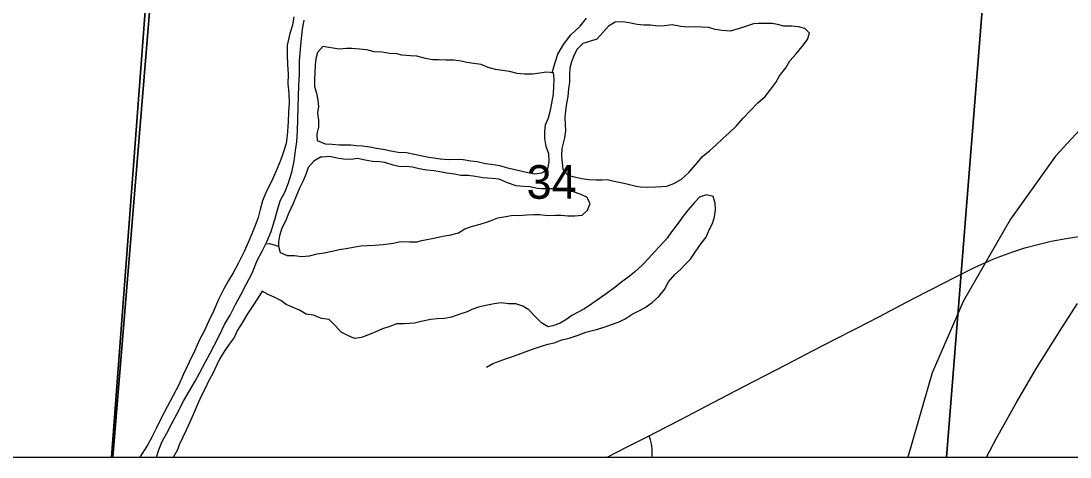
# Model space of a CAD drawing. Extents: x 0 to 1067, y 0 to 440.
# Drawn here: x 799.345 to 800.649, y 350.802 to 351.344 of the extents above; entities that cross this region are included whole.
import ezdxf

# ---------------------------------------------------------------- set-up
doc = ezdxf.new("R2010")
doc.units = 0
for name, color, linetype in [('GM_X_Major_River', 7, 'Continuous'), ('GM_X_Minor_Lake', 7, 'Continuous'), ('GM_X_Minor_River', 7, 'Continuous'), ('GM_X_Rail_Line', 7, 'Continuous'), ('GM_X_Section_Text', 7, 'Continuous'), ('GM_X_State_Route', 7, 'Continuous'), ('GM_X_Township_Road', 7, 'Continuous'), ('GM_X_US_Shield', 7, 'Continuous')]:
    doc.layers.add(name, color=color, linetype=linetype)

msp = doc.modelspace()

# ---------------------------------------------------------------- linework, layer by layer
at = {"layer": 'GM_X_Major_River'}
for points in [[(799.6839, 351.3498), (799.6825, 351.3392), (799.6789, 351.329), (799.6756, 351.3142), (799.6758, 351.3024), (799.6763, 351.2903), (799.6769, 351.2785), (799.6766, 351.2663), (799.6776, 351.2545), (799.6781, 351.2423), (799.6775, 351.2317), (799.6769, 351.2184), (799.6758, 351.202), (799.6745, 351.1921), (799.6713, 351.1819), (799.6673, 351.171), (799.6613, 351.1562), (799.6561, 351.1449), (799.6498, 351.1321), (799.645, 351.1208), (799.6422, 351.1098), (799.6397, 351.0999), (799.6361, 351.0901), (799.6317, 351.0799), (799.6273, 351.069), (799.6222, 351.0576), (799.6147, 351.0429), (799.6084, 351.0312), (799.6028, 351.0215), (799.5969, 351.0113), (799.5902, 350.9981)], [(799.5389, 350.8563), (799.5472, 350.8722), (799.5543, 350.8846), (799.5613, 350.8963), (799.5668, 350.9064), (799.5743, 350.9204), (799.5795, 350.9306), (799.585, 350.9407), (799.5917, 350.9536), (799.598, 350.9671), (799.6047, 350.9784), (799.6114, 350.992), (799.6185, 351.0048), (799.6248, 351.0165), (799.6323, 351.0308), (799.6383, 351.0467), (799.6446, 351.058), (799.6506, 351.0697), (799.6558, 351.0825), (799.6606, 351.0977), (799.6635, 351.1079), (799.6671, 351.1208), (799.673, 351.1317), (799.6774, 351.143), (799.6815, 351.1563), (799.6844, 351.1699), (799.6862, 351.1832), (799.6879, 351.1942), (799.6885, 351.2079), (799.6892, 351.2223), (799.6897, 351.2512), (799.6903, 351.2634), (799.691, 351.2786), (799.6909, 351.2942), (799.6918, 351.3044), (799.6932, 351.3185), (799.695, 351.3341), (799.6967, 351.3454)], [(799.5902, 350.9981), (799.5843, 350.9837), (799.5783, 350.9717), (799.5724, 350.9585), (799.5668, 350.9479), (799.5609, 350.9347), (799.5538, 350.92), (799.5466, 350.9045), (799.541, 350.8917), (799.5269, 350.8653), (799.519, 350.8506), (799.513, 350.8374), (799.5075, 350.8268), (799.502, 350.817), (799.4953, 350.8065), (799.4926, 350.8021)], [(799.5132, 350.8021), (799.5163, 350.8111), (799.5203, 350.8213), (799.5259, 350.8318), (799.5329, 350.8446), (799.5389, 350.8563)]]:
    msp.add_lwpolyline(points, dxfattribs=at)
at = {"layer": 'GM_X_Minor_Lake'}
for points in [[(800.2609, 351.2426), (800.2702, 351.2506), (800.2771, 351.2596), (800.2833, 351.2679), (800.288, 351.2762), (800.2957, 351.2863), (800.3008, 351.295), (800.3089, 351.3036), (800.3162, 351.3127), (800.3228, 351.3213), (800.3252, 351.3292), (800.3195, 351.335), (800.3116, 351.337), (800.3029, 351.3379), (800.2934, 351.338), (800.2854, 351.34), (800.279, 351.3412), (800.2615, 351.3415), (800.2558, 351.3408), (800.2459, 351.3375), (800.2368, 351.3346), (800.2265, 351.3317), (800.2166, 351.3326), (800.2079, 351.3338), (800.2, 351.3362), (800.1916, 351.3367), (800.1829, 351.3372), (800.1746, 351.3369), (800.1651, 351.3378), (800.1545, 351.3395), (800.145, 351.3385), (800.1366, 351.3382), (800.1275, 351.3391), (800.1192, 351.3392), (800.1108, 351.34), (800.101, 351.3421), (800.0926, 351.3433), (800.0835, 351.3431), (800.0755, 351.3382), (800.0685, 351.33), (800.0608, 351.3217), (800.0517, 351.3188), (800.0433, 351.3163), (800.036, 351.3091), (800.0321, 351.3012), (800.0293, 351.2936), (800.0273, 351.2857), (800.0268, 351.2774), (800.0267, 351.2682), (800.0258, 351.2599), (800.0249, 351.2504), (800.0233, 351.2417), (800.022, 351.2326), (800.0211, 351.2243), (800.0214, 351.2155), (800.0217, 351.2079), (800.0208, 351.1992), (800.0172, 351.186)], [(799.7202, 351.3126), (799.7136, 351.3054), (799.7113, 351.2975), (799.7104, 351.2899), (799.7103, 351.2804), (799.7098, 351.2713), (799.7096, 351.263), (799.7122, 351.2546), (799.714, 351.2458), (799.7146, 351.2382), (799.7134, 351.2302), (799.7148, 351.2211), (799.7146, 351.2124), (799.7126, 351.204), (799.7129, 351.1957), (799.7231, 351.1918), (799.7318, 351.1913), (799.7405, 351.1904), (799.7493, 351.1903), (799.7549, 351.1906), (799.7614, 351.1897), (799.7694, 351.1892), (799.7784, 351.188), (799.7868, 351.1864), (799.7951, 351.1851), (799.8046, 351.1831), (799.8137, 351.1814), (799.8243, 351.1809), (799.8341, 351.1789), (799.8436, 351.1769), (799.8519, 351.1752), (799.858, 351.1744), (799.8659, 351.1728), (799.8762, 351.1723), (799.8853, 351.1725), (799.8944, 351.172), (799.9042, 351.1704), (799.9122, 351.1695), (799.9224, 351.1671), (799.9296, 351.1662), (799.9402, 351.1646), (799.9482, 351.1622), (799.9663, 351.1581), (799.975, 351.1558), (799.9837, 351.1545), (799.9925, 351.1555), (799.9975, 351.159)], [(799.9975, 351.159), (800.0001, 351.1607), (800.0014, 351.1691), (800.0012, 351.1793), (799.9979, 351.1885), (799.9961, 351.1984), (799.9962, 351.2067), (799.9971, 351.2151), (800.0006, 351.2242), (800.0031, 351.2336), (800.0047, 351.2423), (800.0071, 351.2533), (800.0073, 351.2628), (800.0078, 351.2719), (800.0071, 351.2799), (799.9984, 351.2808), (799.99, 351.2794), (799.9813, 351.2783), (799.971, 351.2785), (799.9619, 351.279), (799.9521, 351.2818), (799.9347, 351.2843), (799.9256, 351.2867), (799.9169, 351.2902), (799.9078, 351.2915), (799.8991, 351.2927), (799.8923, 351.2943), (799.8832, 351.2956), (799.8733, 351.2957), (799.8642, 351.2962), (799.8566, 351.2963), (799.8479, 351.2979), (799.837, 351.3008), (799.829, 351.3012), (799.8184, 351.3021), (799.8123, 351.3034), (799.8032, 351.3042), (799.7937, 351.3055), (799.7839, 351.306), (799.7748, 351.3084), (799.7657, 351.3093), (799.7562, 351.3102), (799.7494, 351.3103), (799.7403, 351.3096), (799.7202, 351.3126)], [(800.0172, 351.186), (800.0167, 351.1772), (800.0177, 351.1681), (800.0187, 351.1597), (800.0247, 351.1528), (800.0327, 351.1504), (800.0421, 351.1484), (800.0508, 351.1472), (800.0599, 351.1467), (800.0679, 351.1469), (800.0736, 351.1472), (800.0823, 351.1452), (800.0906, 351.1436), (800.0997, 351.1416), (800.1096, 351.1388), (800.1152, 351.138), (800.1243, 351.1378), (800.1342, 351.1381), (800.1418, 351.1384), (800.1479, 351.139), (800.1567, 351.1423), (800.1662, 351.1479), (800.1751, 351.1562), (800.1836, 351.1655), (800.1924, 351.1757), (800.2009, 351.1828), (800.209, 351.1899), (800.2174, 351.1981), (800.2255, 351.2052), (800.2347, 351.2142), (800.2428, 351.2236), (800.2517, 351.2326), (800.2609, 351.2426)], [(799.7172, 351.1751), (799.7091, 351.1699), (799.7018, 351.1624), (799.6994, 351.1549), (799.6955, 351.1458), (799.6912, 351.1364), (799.6869, 351.1265), (799.6833, 351.1175), (799.6802, 351.1111), (799.6775, 351.105), (799.6735, 351.0956), (799.6689, 351.0869), (799.6661, 351.0774), (799.6648, 351.0699), (799.6651, 351.0642), (799.6669, 351.0566), (799.6756, 351.0526), (799.6847, 351.0529), (799.6934, 351.0516), (799.7037, 351.0523), (799.7132, 351.0548), (799.7216, 351.0562), (799.7315, 351.058), (799.7406, 351.0601), (799.749, 351.0615), (799.7577, 351.0633), (799.7672, 351.0647), (799.7756, 351.065), (799.7847, 351.0656), (799.795, 351.0666), (799.8014, 351.0673), (799.8079, 351.0683), (799.8167, 351.0701), (799.8277, 351.0696), (799.8372, 351.0699), (799.8433, 351.0713), (799.86, 351.0749), (799.8695, 351.0766), (799.8794, 351.0784), (799.8886, 351.0809), (799.8966, 351.0858), (799.905, 351.0887), (799.9157, 351.0916), (799.9237, 351.0942), (799.9294, 351.0964), (799.9378, 351.0997), (799.9477, 351.1014), (799.9564, 351.1028), (799.964, 351.1027), (799.9739, 351.1034), (799.9823, 351.1036), (799.9899, 351.1039), (799.999, 351.1027), (800.0093, 351.1029)], [(800.0093, 351.1029), (800.0164, 351.1028), (800.0248, 351.1019), (800.0335, 351.1022), (800.0426, 351.1028), (800.0492, 351.1092), (800.0527, 351.1175), (800.0482, 351.1252), (800.0399, 351.1291), (800.032, 351.1318), (800.0259, 351.1327), (800.0172, 351.1339), (800.0089, 351.1356), (799.9922, 351.1358), (799.9865, 351.1362), (799.9778, 351.1382), (799.9695, 351.1387), (799.9604, 351.1396), (799.9498, 351.1432), (799.9392, 351.1475), (799.9305, 351.1484), (799.9191, 351.1493), (799.91, 351.1509), (799.9009, 351.1522), (799.8918, 351.1523), (799.8839, 351.1539), (799.8744, 351.1552), (799.868, 351.1564), (799.8585, 351.1581), (799.8494, 351.1589), (799.8399, 351.1606), (799.8316, 351.1626), (799.8229, 351.1635), (799.8164, 351.1632), (799.8074, 351.1652), (799.7972, 351.1684), (799.7907, 351.1692), (799.782, 351.1697), (799.7729, 351.1713), (799.7634, 351.1734), (799.7551, 351.172), (799.7456, 351.1725), (799.7373, 351.1737), (799.7286, 351.1757), (799.7198, 351.1751), (799.7172, 351.1751)], [(800.145, 351.0103), (800.15, 351.0198), (800.1578, 351.0292), (800.1647, 351.0355), (800.1708, 351.0415), (800.1774, 351.0483), (800.1832, 351.0569), (800.1906, 351.0678), (800.1967, 351.0757), (800.2007, 351.0848), (800.2046, 351.0927), (800.2073, 351.101), (800.2082, 351.1094), (800.208, 351.1177), (800.2054, 351.1261), (800.1971, 351.1281), (800.1887, 351.1252), (800.1822, 351.1185), (800.1744, 351.1095), (800.1683, 351.1016), (800.1609, 351.0914), (800.1536, 351.0824), (800.1481, 351.0745), (800.1396, 351.0647), (800.1319, 351.0565), (800.1254, 351.0493), (800.1173, 351.0407), (800.1077, 351.0321), (800.0992, 351.0254), (800.092, 351.0202), (800.0831, 351.0131), (800.0739, 351.0063), (800.0643, 350.9993), (800.0548, 350.9925), (800.0456, 350.9866), (800.0368, 350.9818), (800.0299, 350.9781), (800.0222, 350.9728), (800.0142, 350.968), (800.0062, 350.9651), (800.0005, 350.964), (799.9922, 350.9691), (799.9839, 350.9771), (799.9764, 350.9852), (799.9689, 350.9899), (799.9602, 350.9927), (799.9511, 350.9928), (799.942, 350.9937), (799.9333, 350.9926), (799.923, 350.9905), (799.9135, 350.9887), (799.9055, 350.9854), (799.8994, 350.9828), (799.8906, 350.9799), (799.8799, 350.9762), (799.8715, 350.9745), (799.8624, 350.9738), (799.8544, 350.9732), (799.8422, 350.9707), (799.8339, 350.9685), (799.8217, 350.9679), (799.8122, 350.9676), (799.8034, 350.9643), (799.7943, 350.9614), (799.7859, 350.9577), (799.7767, 350.9541), (799.7683, 350.9508), (799.7596, 350.9494), (799.7513, 350.9533), (799.743, 350.9576), (799.7359, 350.9652), (799.728, 350.9733), (799.7185, 350.9746), (799.7083, 350.9785), (799.6993, 350.9798), (799.691, 350.9848), (799.683, 350.988), (799.6744, 350.9919), (799.668, 350.9969), (799.6604, 351.0004), (799.6521, 351.0043), (799.6446, 351.0082)], [(799.9238, 350.9138), (799.9315, 350.9186), (799.9406, 350.9219), (799.9487, 350.9248), (799.957, 350.9274), (799.9628, 350.9296), (799.9719, 350.9329), (799.9822, 350.9365), (799.9906, 350.9395), (800.0001, 350.9424), (800.0078, 350.9442), (800.0173, 350.9478), (800.0264, 350.95), (800.0375, 350.9537), (800.0471, 350.9573), (800.0604, 350.9609), (800.0699, 350.9635), (800.0791, 350.9668), (800.0886, 350.9701), (800.0959, 350.9738), (800.1047, 350.9797), (800.1131, 350.9838), (800.1211, 350.9882), (800.1296, 350.9942), (800.138, 351.0017), (800.145, 351.0103)], [(799.6446, 351.0082), (799.6392, 350.9996), (799.633, 350.9902), (799.6264, 350.98), (799.6198, 350.9691), (799.6139, 350.96), (799.61, 350.9506), (799.6038, 350.9423), (799.5984, 350.9344), (799.5922, 350.9246), (799.5879, 350.9159), (799.5832, 350.9061), (799.5785, 350.8971), (799.5738, 350.8873), (799.5692, 350.8786), (799.5652, 350.8695), (799.5605, 350.8586), (799.5578, 350.8522), (799.5543, 350.8446), (799.55, 350.8356), (799.5457, 350.8261), (799.5413, 350.8171), (799.5394, 350.811), (799.5343, 350.8023), (799.5342, 350.8021)]]:
    msp.add_lwpolyline(points, dxfattribs=at)
at = {"layer": 'GM_X_Minor_River'}
for points in [[(800.0054, 351.2801), (800.0092, 351.2928), (800.0124, 351.303), (800.0194, 351.3154), (800.0283, 351.3271), (800.0402, 351.3379), (800.0479, 351.3481)], [(799.6493, 351.0672), (799.6538, 351.0677), (799.6651, 351.0645)]]:
    msp.add_lwpolyline(points, dxfattribs=at)
at = {"layer": 'GM_X_Rail_Line'}
for points in [[(801.3639, 351.9272), (801.2652, 351.8274), (801.0334, 351.5931), (800.8184, 351.3732), (800.6866, 351.2365), (800.6313, 351.1762), (800.5752, 351.098), (800.517, 350.9963), (800.4777, 350.9069), (800.4476, 350.8021)], [(800.5453, 350.8021), (800.5578, 350.8257), (800.5831, 350.8709), (800.6076, 350.9126), (800.6371, 350.9595), (800.6587, 350.9932)]]:
    msp.add_lwpolyline(points, dxfattribs=at)
at = {"layer": 'GM_X_State_Route'}
for points in [[(800.5349, 351.0398), (800.5472, 351.0453), (800.5515, 351.0472), (800.5601, 351.0507), (800.5782, 351.0573), (800.5929, 351.0621), (800.6091, 351.0665), (800.626, 351.0706), (800.6443, 351.0741), (800.6602, 351.0765), (800.68, 351.0785), (800.6959, 351.0795), (800.7122, 351.0801)], [(800.4868, 351.0157), (800.5106, 351.0278), (800.5322, 351.0386), (800.5349, 351.0398)], [(800.47, 351.0071), (800.4824, 351.0135), (800.4868, 351.0157)], [(800.0736, 350.8021), (800.0987, 350.8148), (800.126, 350.8283), (800.1346, 350.8329), (800.1655, 350.8489), (800.1969, 350.8653), (800.243, 350.8896), (800.2977, 350.9177), (800.3291, 350.9341), (800.3573, 350.9486), (800.3832, 350.9621), (800.4125, 350.977), (800.446, 350.9947), (800.47, 351.0071)]]:
    msp.add_lwpolyline(points, dxfattribs=at)
at = {"layer": 'GM_X_Township_Road'}
for points in [[(798.0401, 353.8616), (798.0401, 350.8021), (799.4572, 350.8021), (799.5626, 352.1981), (799.6113, 352.6978), (799.7017, 353.7093)], [(799.7017, 353.7093), (799.6113, 352.6978), (799.5626, 352.1981), (799.4572, 350.8021), (804.8401, 350.8021)], [(800.1294, 350.8021), (800.1295, 350.8035), (800.1296, 350.8092), (800.1295, 350.8124), (800.1292, 350.8155), (800.1288, 350.8187), (800.1275, 350.8234), (800.126, 350.8283)]]:
    msp.add_lwpolyline(points, dxfattribs=at)
at = {"layer": 'GM_X_US_Shield'}
for points in [[(798.4223, 350.8021), (799.4588, 350.8021), (799.5337, 351.7084), (798.5186, 351.8037)], [(799.4588, 350.8021), (800.4958, 350.8021), (800.5587, 351.5925), (799.5337, 351.7084)], [(800.4958, 350.8021), (801.4897, 350.8021), (801.5595, 351.4988), (800.5587, 351.5925)]]:
    msp.add_lwpolyline(points, close=True, dxfattribs=at)

# ---------------------------------------------------------------- texts
at = {"layer": 'GM_X_Section_Text'}
msp.add_text('34', height=0.04186, rotation=0, dxfattribs=at).set_placement((799.9735, 351.1233))

doc.saveas('drawing.dxf')
